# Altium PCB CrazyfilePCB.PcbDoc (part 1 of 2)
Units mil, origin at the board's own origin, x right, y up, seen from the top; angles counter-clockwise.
Board outline 3667.19 x 3670.52 mil, 4 copper layers (Top Layer, GND, VCC, Bottom Layer); 99 components, 96 nets, 358 pads, 80 vias.
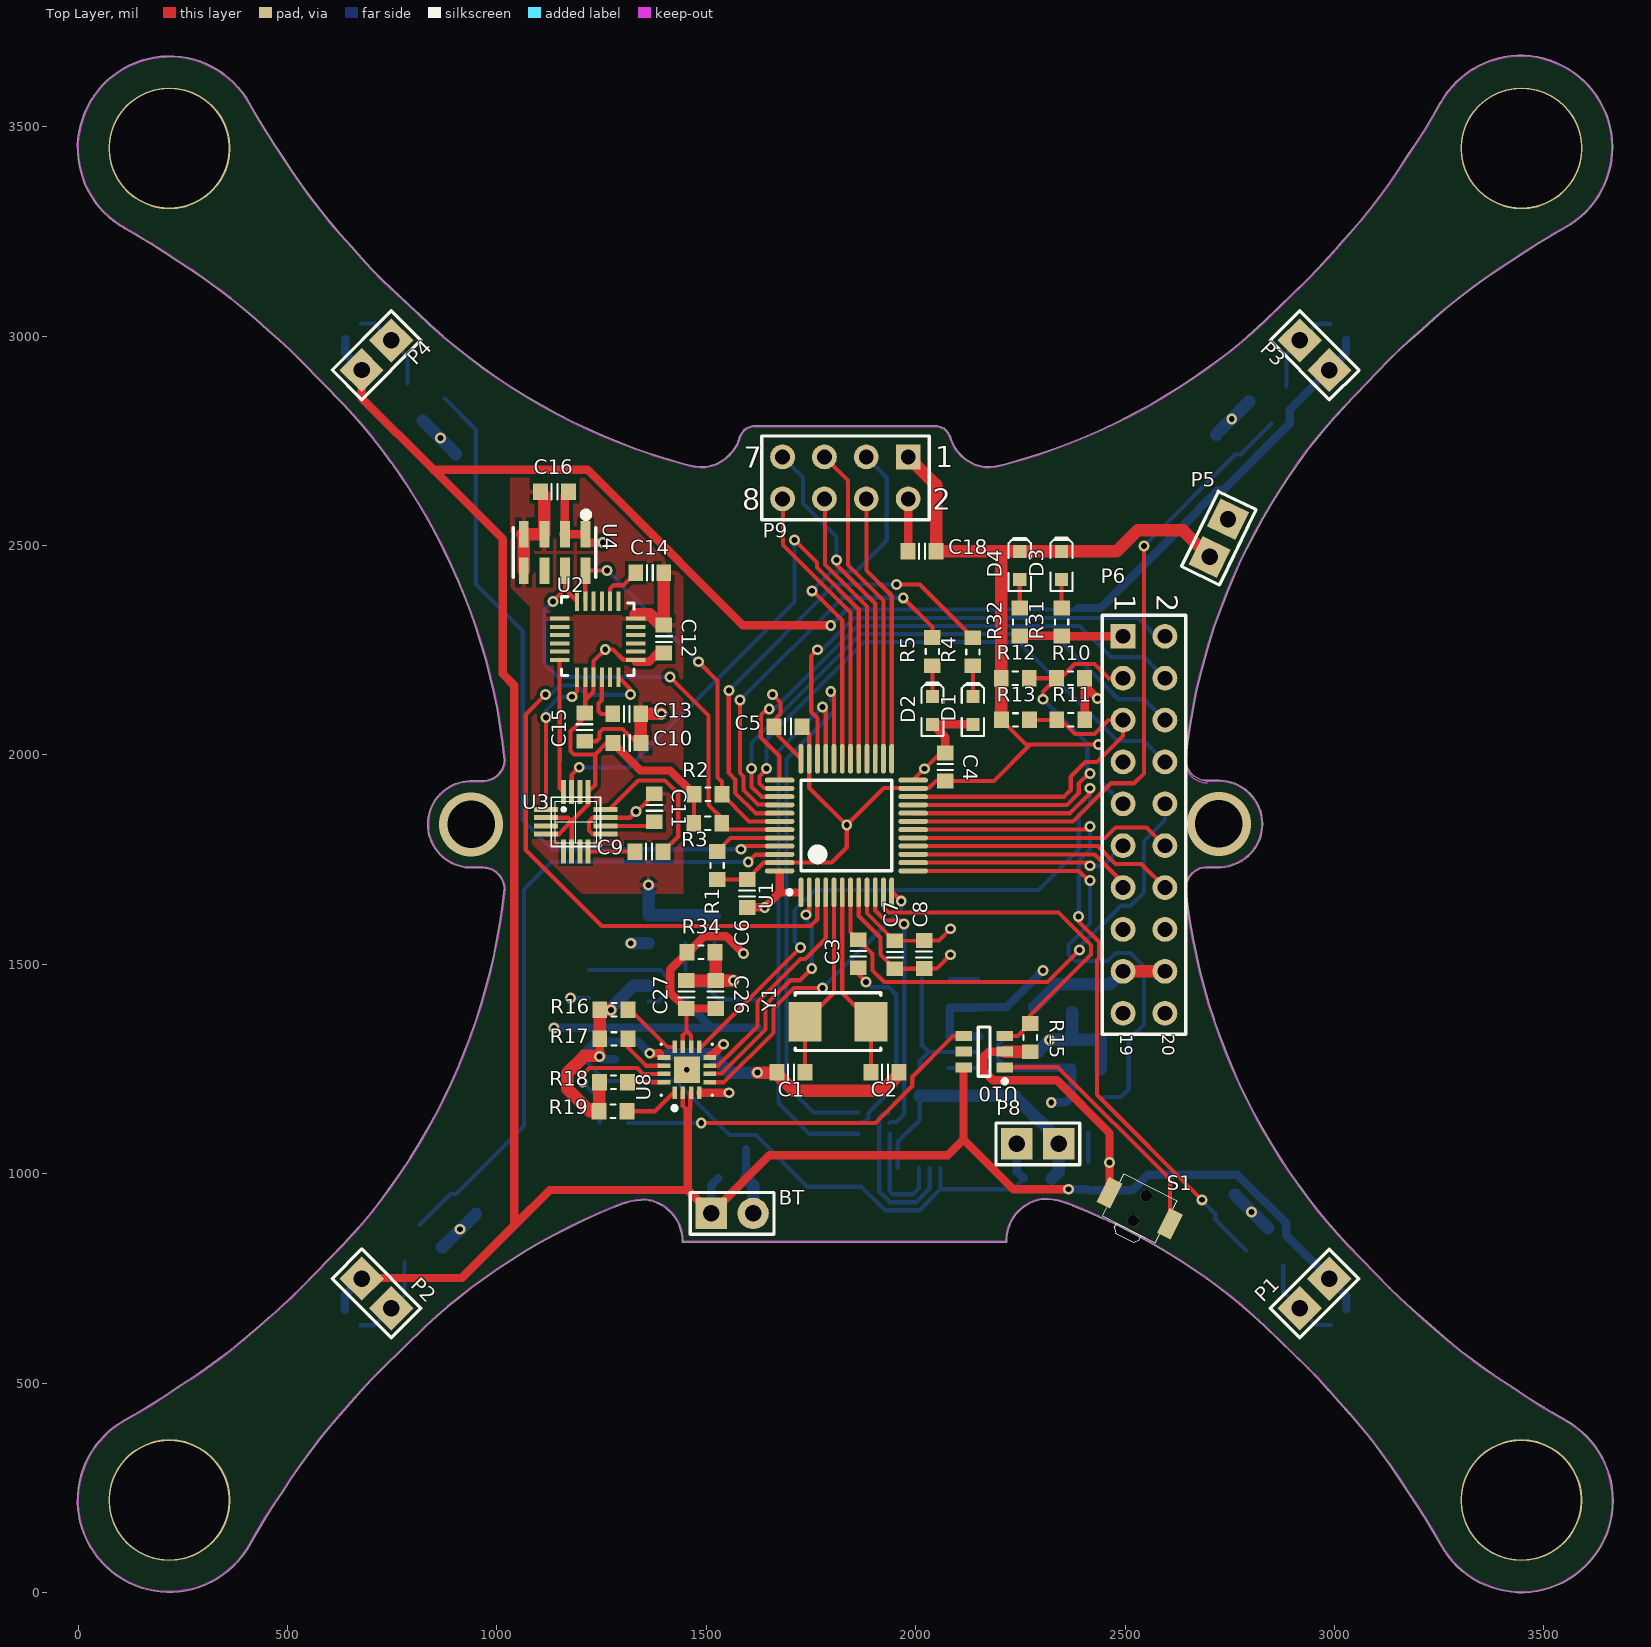
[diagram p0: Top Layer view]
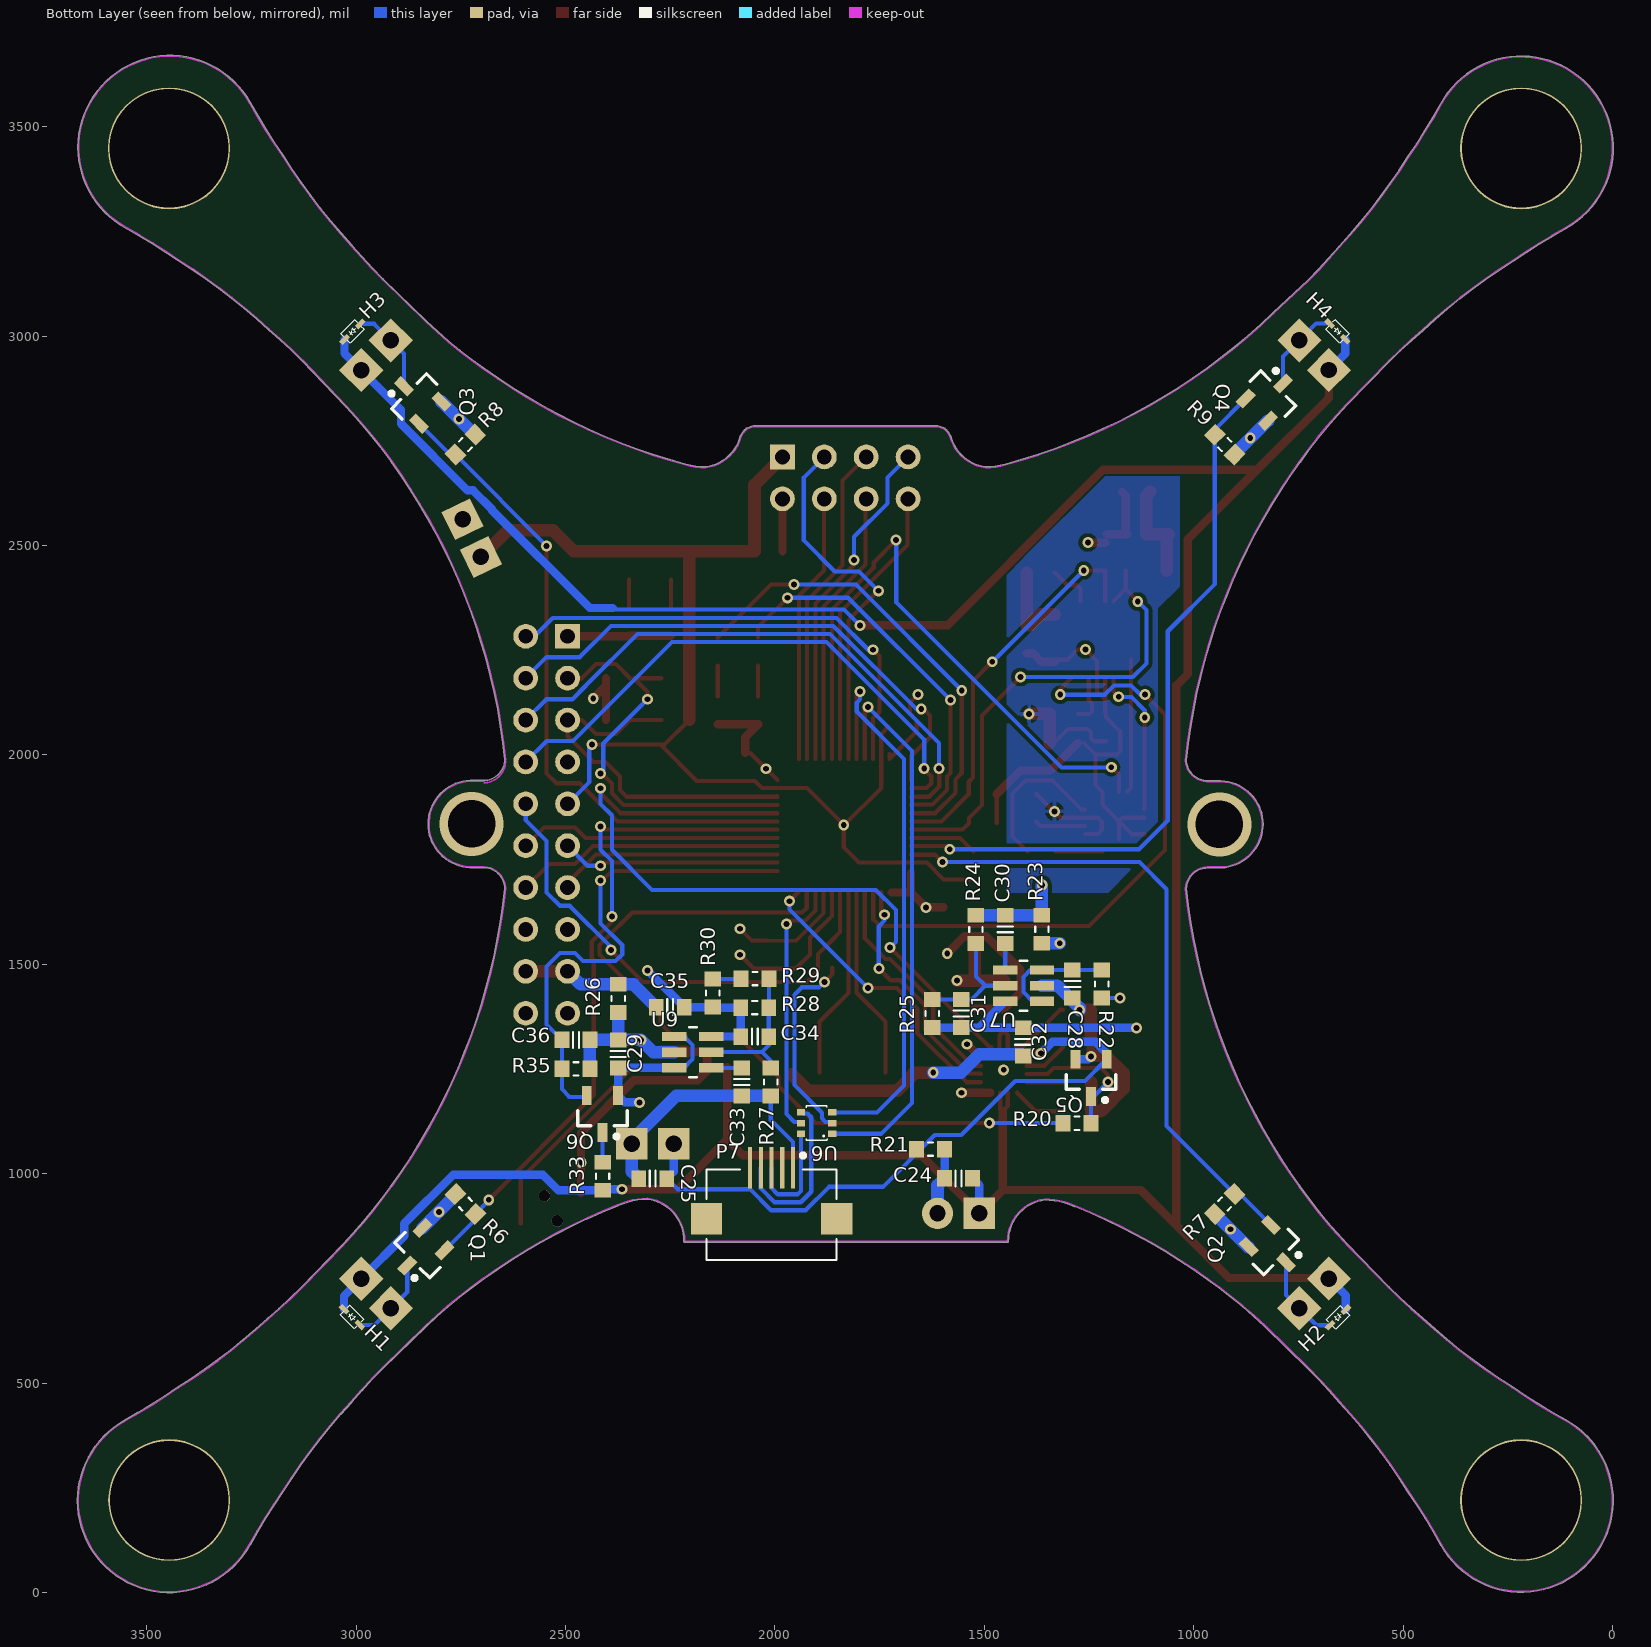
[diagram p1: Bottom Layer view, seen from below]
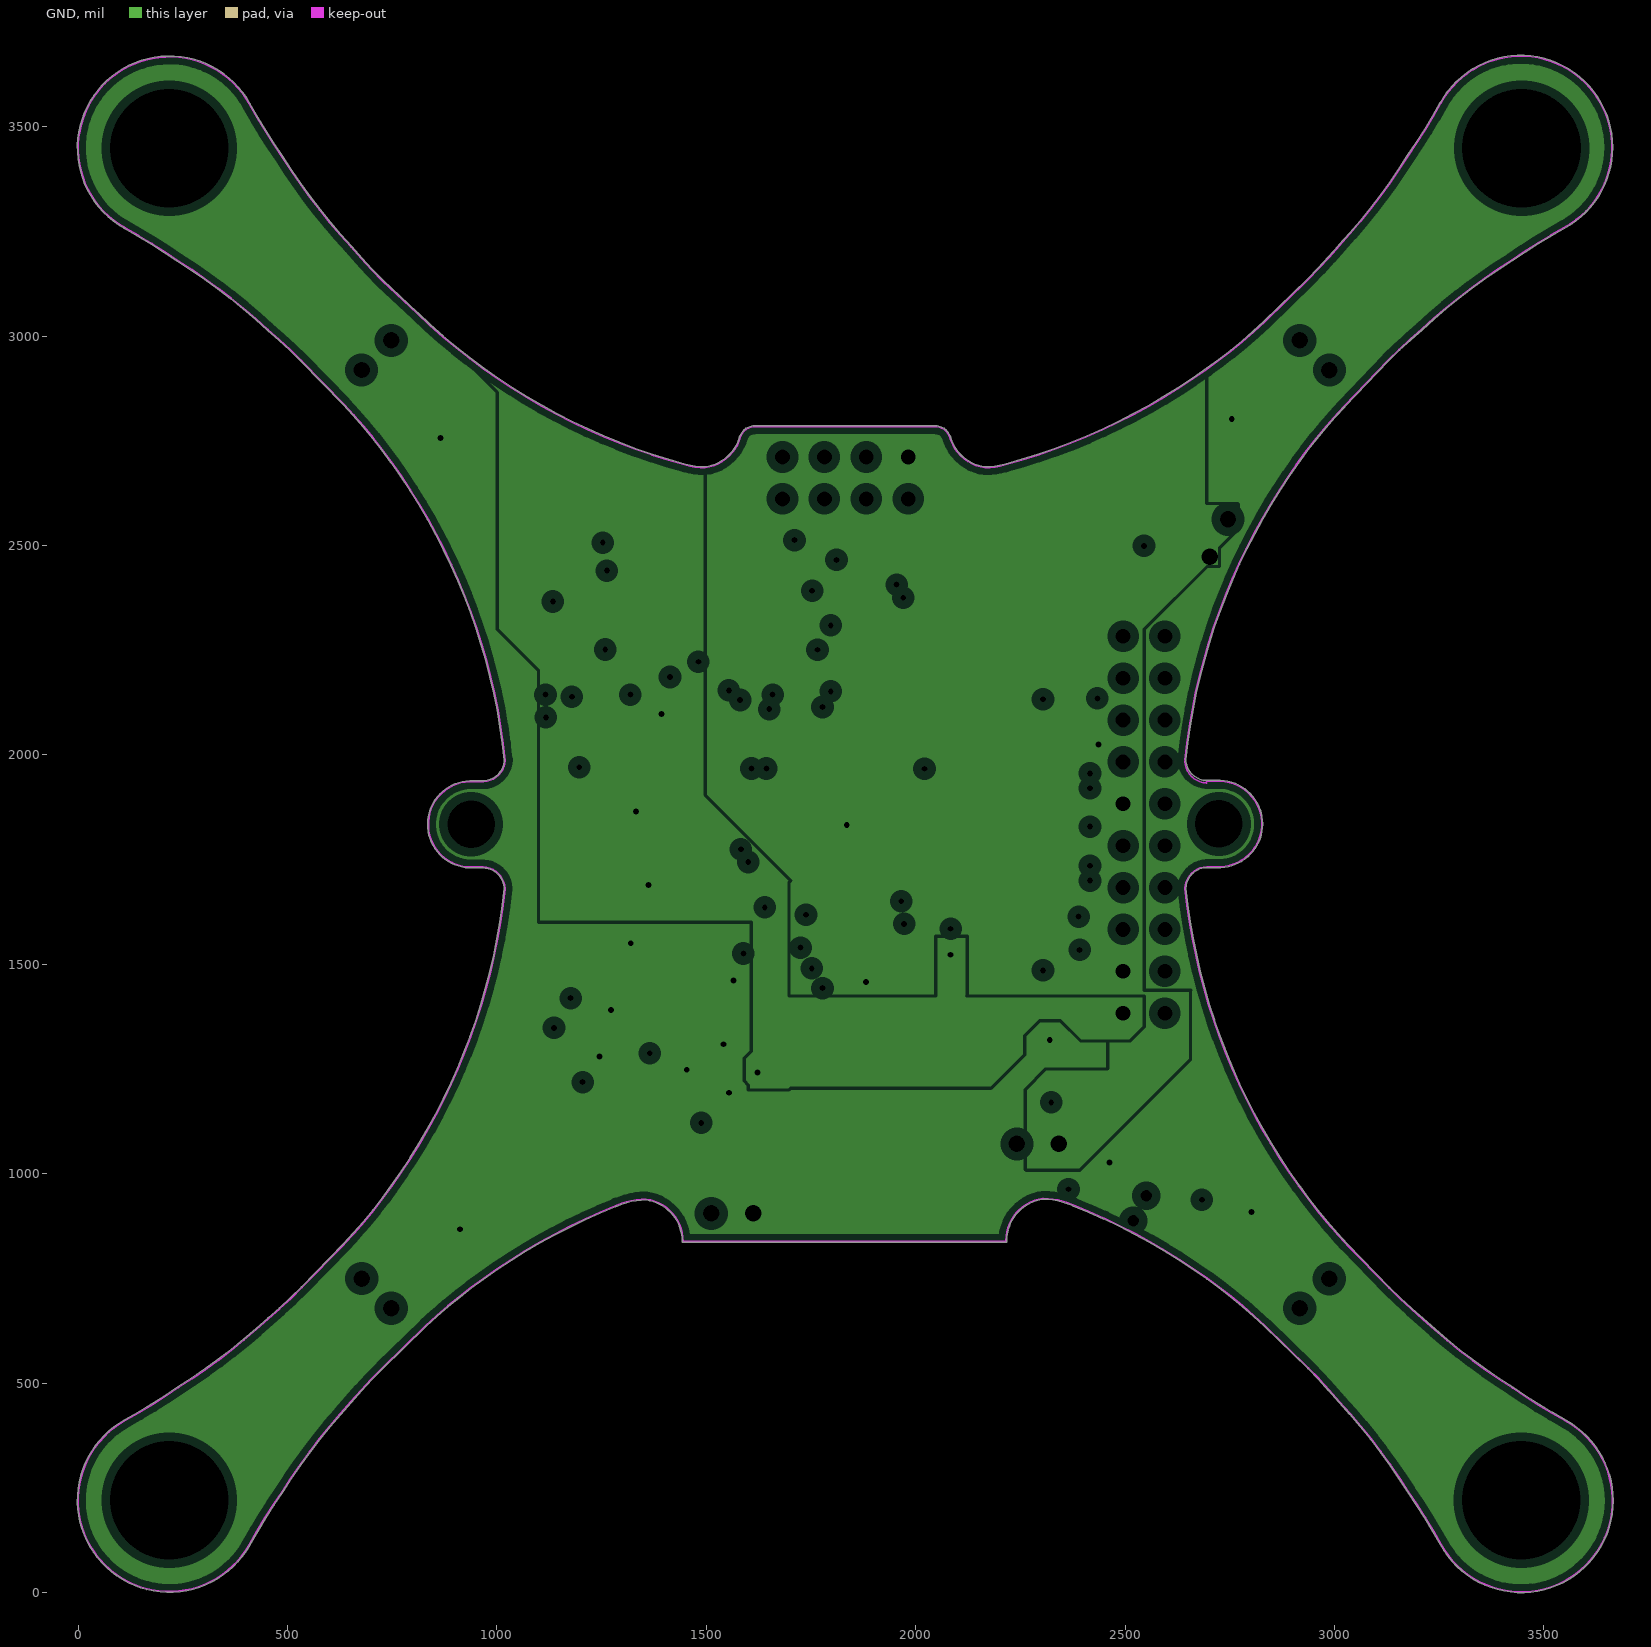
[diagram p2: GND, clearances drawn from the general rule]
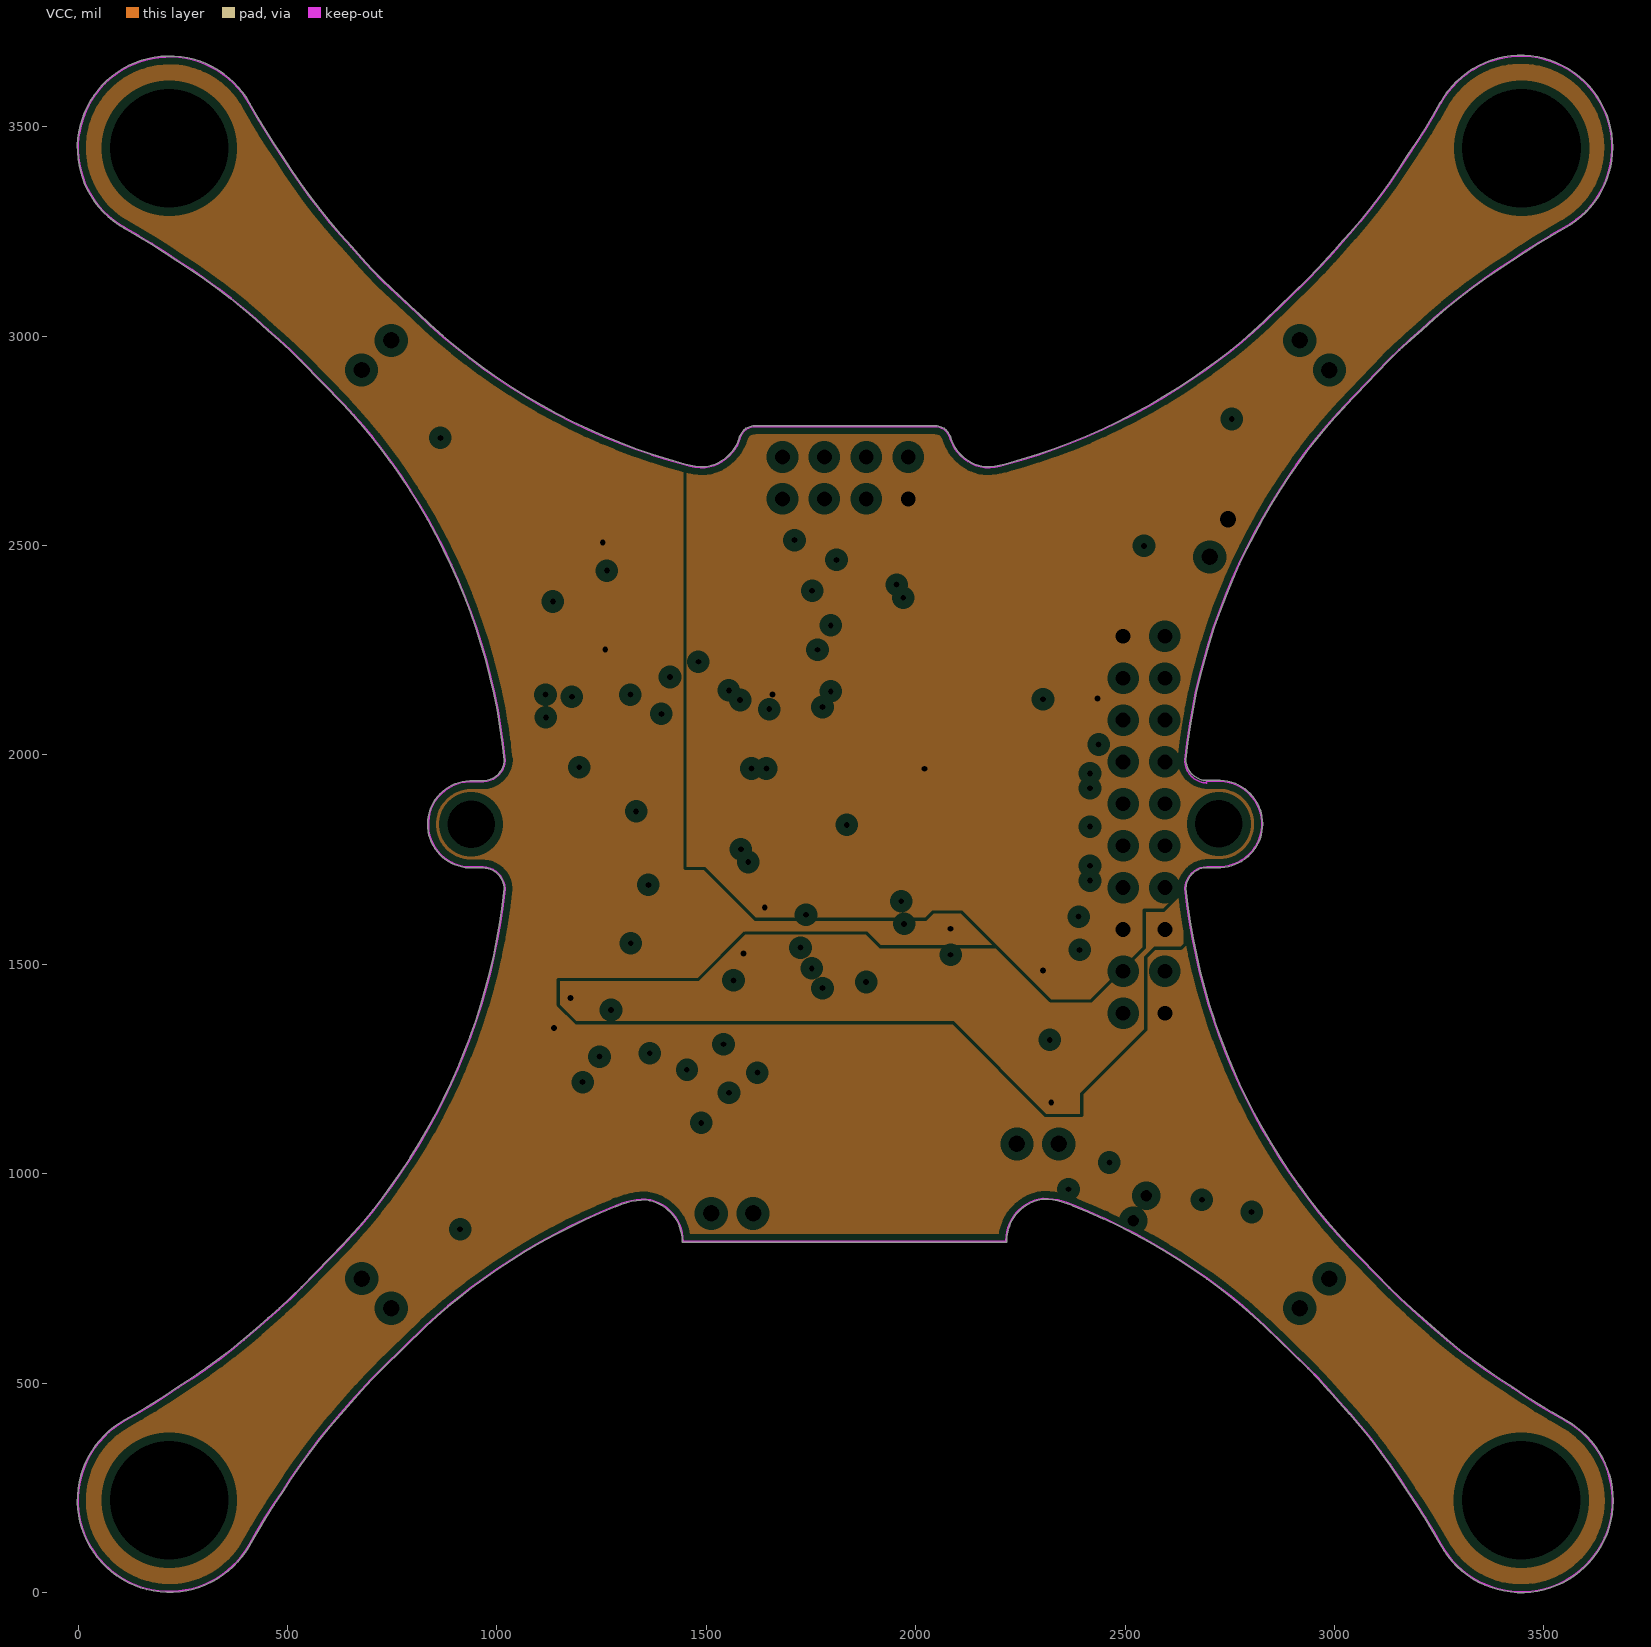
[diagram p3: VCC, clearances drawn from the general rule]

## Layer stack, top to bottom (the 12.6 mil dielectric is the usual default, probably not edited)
Top Layer: signal copper 1.4
Dielectric: core 12.6, FR-4, Dk 4.8
GND: plane copper 1.4, net (Multiple Nets)
Dielectric: prepreg 12.6, FR-4, Dk 4.8
VCC: plane copper 1.4, net (Multiple Nets)
Dielectric: core 12.6, FR-4, Dk 4.8
Bottom Layer: signal copper 1.4

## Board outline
112.49,412.56 ccw(c218.07,219.96) 409.62,112.5 ccw(c408.54,114.15) 410.27,113.19 cw(c1713.74,-607.99) 488.67,239.56 ccw(c487.04,240.69) 488.7,239.6 ccw(c487.05,240.7) 488.73,239.64 cw(c1713.74,-529.25) 652.96,453.91 ccw(c651.5,455.25) 653.04,454 cw(c1713.74,-450.51) 727.04,534.2 830.81,635.06 cw(c1674.37,-253.66) 968.41,747.86 ccw(c967.28,749.48) 968.43,747.87 ccw(c967.28,749.48) 968.44,747.88 cw(c1832.24,-448.94) 1284.14,921.5 ccw(c1283.4,923.34) 1285.22,922.56 ccw(c1286.18,924.29) 1286.99,922.48 cw(c1356.01,767.66) 1356.47,937.17 cw(c1342.79,838.21) 1442.7,838.21 cw(c1342.79,838.21) 1442.7,838.12 cw(c1342.79,838.21) 1442.7,838.1 cw(c1444.68,838.1) 1442.7,838.12 1442.7,838.1 ccw(c1444.68,838.1) 1444.73,836.12 2215.48,836.12 ccw(c2215.48,838.1) 2217.46,838.1 ccw(c2215.48,838.1) 2217.3,838.89 ccw(c2215.48,839.68) 2217.46,839.68 cw(c2317.36,839.78) 2303.82,938.76 ccw(c2303.55,940.73) 2303.94,938.78 ccw(c2304.34,940.73) 2304.34,938.74 cw(c2304.93,769.24) 2373.96,924.05 ccw(c2374.76,925.87) 2374.14,923.98 ccw(c2375.52,925.4) 2374.79,923.56 cw(c1832.24,-448.94) 2695.26,748.27 2695.27,748.27 ccw(c2696.42,749.88) 2695.28,748.26 cw(c1989.33,-253.27) 2832.89,635.45 2936.66,534.59 2936.67,534.58 2936.66,534.59 cw(c1949.96,-450.12) 3010.66,454.39 ccw(c3012.2,455.65) 3010.74,454.3 cw(c1949.96,-528.86) 3174.97,240.04 ccw(c3176.65,241.09) 3175,240 ccw(c3176.66,241.08) 3175.03,239.95 cw(c1949.96,-607.6) 3253.42,113.6 3253.43,113.59 ccw(c3446.02,219.17) 3665.66,219.17 ccw(c3446.02,219.17) 3553.49,410.72 ccw(c3551.83,409.64) 3552.79,411.37 cw(c4273.98,1714.84) 3426.42,489.77 ccw(c3425.3,488.14) 3426.38,489.8 ccw(c3425.28,488.15) 3426.34,489.83 cw(c4195.24,1714.84) 3212.08,654.06 ccw(c3210.73,652.6) 3211.98,654.14 cw(c4116.5,1714.84) 3131.79,728.14 3131.8,728.13 3131.79,728.14 3030.93,831.91 3030.92,831.92 3030.93,831.91 cw(c3919.65,1675.47) 2918.12,969.52 ccw(c2916.5,968.38) 2916.33,970.36 ccw(c2914.35,970.51) 2916.34,970.51 ccw(c2914.35,970.51) 2915.96,971.67 cw(c4113.74,1834.92) 2645.28,1681.58 ccw(c2643.31,1681.77) 2645.29,1681.68 cw(c2696.7,1679.41) 2695.21,1730.85 2728.56,1730.97 ccw(c2728.56,1732.95) 2728.84,1730.99 ccw(c2724.37,1834.92) 2828.4,1834.92 ccw(c2724.37,1834.92) 2727.84,1938.89 ccw(c2727.77,1936.91) 2727.49,1938.87 2694.76,1938.87 ccw(c2694.45,1936.91) 2694.52,1938.9 cw(c2696.42,1990.43) 2644.9,1988.16 ccw(c2642.91,1988.07) 2644.86,1988.43 cw(c4113.74,1834.92) 2916.58,2699.77 ccw(c2914.97,2700.93) 2916.95,2700.93 ccw(c2914.97,2700.93) 2916.95,2701.08 cw(c3929.95,1971.8) 3024.64,2831.12 ccw(c3023.2,2832.49) 3024.79,2831.3 ccw(c3023.75,2832.99) 3025.19,2831.63 3129.43,2941.31 cw(c4114.13,1954.61) 3209.62,3015.31 cw(c4114.13,1954.61) 3209.66,3015.34 3209.62,3015.31 ccw(c3208.37,3016.85) 3209.72,3015.39 cw(c4192.87,1954.61) 3423.98,3179.62 ccw(c3422.92,3181.3) 3424.02,3179.65 ccw(c3422.93,3181.31) 3424.06,3179.68 cw(c4271.61,1954.61) 3550.42,3258.07 ccw(c3444.84,3450.67) 3664.48,3450.67 ccw(c3444.84,3450.67) 3253.29,3558.13 ccw(c3254.38,3556.48) 3252.64,3557.44 cw(c1949.17,4278.62) 3174.24,3431.07 ccw(c3175.87,3429.94) 3174.21,3431.03 ccw(c3175.87,3429.93) 3174.19,3430.99 cw(c1949.17,4199.88) 3009.96,3216.72 ccw(c3011.41,3215.38) 3009.88,3216.63 ccw(c1949.17,4121.14) 3009.9,3216.66 3009.88,3216.63 cw(c1949.17,4121.14) 2935.87,3136.43 2935.88,3136.44 2935.87,3136.43 2832.11,3035.57 2832.1,3035.57 2832.11,3035.57 cw(c1988.54,3924.29) 2695.04,2923.15 ccw(c2695.56,2921.24) 2694.4,2922.85 cw(c1832.24,4117.99) 2213.23,2694.43 ccw(c2213.75,2692.51) 2213.19,2694.42 cw(c2165.91,2857.2) 2165.45,2687.69 cw(c2179.13,2786.65) 2082.44,2761.5 ccw(c2080.52,2761) 2081.59,2762.68 ccw(c2034.61,2740.04) 2069.04,2779.21 ccw(c2067.73,2777.72) 2067.97,2779.69 ccw(c2045.24,2740.04) 2044.03,2785.72 ccw(c2045.24,2740.04) 2044,2785.72 2044.06,2785.72 1618.89,2785.72 cw(c1617.68,2740.04) 1618.91,2785.72 1618.89,2785.72 ccw(c1617.68,2740.04) 1594.95,2779.69 ccw(c1595.18,2777.72) 1593.87,2779.21 ccw(c1628.31,2740.04) 1581.32,2762.68 ccw(c1582.39,2761) 1580.47,2761.5 cw(c1483.78,2786.65) 1497.46,2687.69 cw(c1497,2857.2) 1449.72,2694.42 1449.68,2694.43 cw(c1831.69,4115.93) 810.9,3055.47 ccw(c809.52,3054.04) 810.87,3055.5 810.88,3055.48 810.87,3055.5 727.43,3133.68 cw(c1714.13,4118.39) 653.43,3213.87 cw(c1714.13,4118.39) 653.4,3213.91 653.43,3213.87 ccw(c651.89,3212.62) 653.35,3213.97 cw(c1714.13,4197.13) 489.12,3428.23 ccw(c487.44,3427.17) 489.09,3428.27 ccw(c487.43,3427.19) 489.06,3428.31 cw(c1714.13,4275.87) 410.67,3554.67 ccw(c218.07,3449.09) 110.61,3257.54 ccw(c112.27,3258.63) 111.3,3256.89 cw(c-609.88,1953.43) 237.67,3178.5 ccw(c238.8,3180.13) 237.71,3178.47 ccw(c238.81,3180.12) 237.76,3178.44 cw(c-531.14,1953.43) 452.02,3014.21 ccw(c453.36,3015.66) 452.11,3014.13 cw(c-452.4,1953.43) 532.31,2940.12 532.3,2940.14 532.31,2940.12 633.17,2836.36 633.17,2836.35 633.17,2836.36 cw(c-255.55,1992.8) 745.97,2698.74 ccw(c747.59,2699.89) 747.06,2697.98 cw(c-450.83,1834.13) 1018.05,1987.65 ccw(c1020,1987.29) 1018.02,1987.37 cw(c966.5,1989.65) 968.39,1938.11 ccw(c968.46,1936.13) 968.15,1938.09 935.42,1938.09 ccw(c935.14,1936.12) 935.08,1938.1 ccw(c938.54,1834.13) 934.07,1730.2 ccw(c934.36,1732.17) 934.35,1730.18 967.7,1730.06 967.72,1730.06 967.7,1730.06 ccw(c966.22,1678.63) 967.68,1730.06 967.7,1730.06 cw(c966.22,1678.63) 1017.62,1680.9 ccw(c1019.61,1680.98) 1017.63,1680.79 cw(c-450.83,1834.13) 746.95,970.88 ccw(c748.56,969.72) 746.58,969.9 cw(c-254.37,1676.65) 634.35,833.09 634.35,833.1 634.35,833.09 533.49,729.32 cw(c-451.22,1716.02) 453.29,655.32 cw(c-451.22,1716.02) 453.26,655.29 453.29,655.32 ccw(c454.54,653.78) 453.2,655.24 cw(c-529.96,1716.02) 238.94,491.01 ccw(c239.99,489.33) 238.89,490.98 ccw(c239.98,489.32) 238.85,490.95 cw(c-608.7,1716.02)

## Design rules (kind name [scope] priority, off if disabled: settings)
Clearance U8 [Ispad and incomponent ( 'U8' )] p1: gap=6.4
Clearance U6 [Ispad and incomponent ( 'U6' )] p2: gap=9.8
Clearance U3 [IspaD and incomponent ( 'U3' )] p3: gap=6.4
Clearance U2 [Ispad and incomponent ( 'U2' )] p4: gap=9.7
Clearance U1 [Ispad and incomponent ( 'U1' )] p5: gap=7.8
Clearance [All] p6: gap=9
FabricationTestPointUsage TestPointUsage [All] p1: valid=0 allowmultiple=FALSE
FabricationTestpoint Testpoint [All] p1: side=3 testpointundercomponent=TRUE minsize=40 maxsize=100 preferedsize=60 minholesize=0 maxholesize=40 preferedholesize=32 testpointgrid=1 allowsidetop=TRUE allowsidebottom=TRUE usegrid=TRUE gridtolerance=0.01
HoleSize [All] p1: absolutevalues=TRUE maxlimit=200 minlimit=1 maxpercent=80.000 minpercent=20.000
PlaneClearance [All] p1: clearance=20
PlaneConnect [All] p1: planeconnectstyle=Relief reliefexpansion=20 reliefentries=4 reliefconductorwidth=10 reliefairgap=10
PolygonConnect [All] p1: connectstyle=Relief reliefconductorwidth=10 reliefentries=4 polygonreliefangle="90 Angle"
RoutingVias [All] p1: holewidth=28 width=50 viastyle="Through Hole" minholewidth=28 minwidth=50 maxholewidth=228 maxwidth=250
SilkscreenOverComponentPads [All] p1: minsilkscreentomaskgap=10
SolderMaskExpansion [All] p1: expansion=4
Width VCC_Width [InNet('VCC')] p1: maxlimit=30 minlimit=10 preferedwidth=20
Width POWER_5V_Width [InNet('VCOM')] p2: maxlimit=30 minlimit=10 preferedwidth=20
Width POWER_3V3_Width [InNet('VCCA')] p3: maxlimit=30 minlimit=9 preferedwidth=20
Width GND_Width [InNet('GND')] p4: maxlimit=40 minlimit=10 preferedwidth=30
Width Width_+BATT [InNet('+BATT')] p5: maxlimit=30 minlimit=10 preferedwidth=20
22 further rules are at their usual default settings.

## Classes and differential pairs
component class "crazefile contal wireless": C18 P9
component class "crazefile contal power": BT C24 C25 C26 C27 C28 C29 C30 C31 C32 C33 C34 C35 C36 D3 D4 P7 P8 Q5 Q6 R15 R16 R17 R18 R19 R20 R21 R22 R23 R24 R25 R26 R27 R28 R29 R30 R31 R32 R33 R34 R35 S1 U6 U7 U8 U9 U10
component class "crazefile contal imu": C9 C10 C11 C12 C13 C14 C15 C16 U2 U3 U4
component class "crazefile contal board": C1 C2 C3 C4 C5 C6 C7 C8 D1 D2 H1 H2 H3 H4 P1 P2 P3 P4 P5 P6 Q1 Q2 Q3 Q4 R1 R2 R3 R4 R5 R6 R7 R8 R9 R10 R11 R12 R13 U1 Y1

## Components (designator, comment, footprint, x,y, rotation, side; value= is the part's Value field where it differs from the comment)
BT "Battery" BATTERY 1511.9,905 r0 top locked
C1 "Cap" CAP_0603 1702.12,1241.73 r0 top
C2 "Cap" CAP_0603 1926.82,1241.73 r180 top
C3 "Cap" CAP_0603 1863.08,1525.04 r270 top
C4 "Cap" CAP_0603 2070.78,1971.25 r90 top
C5 "Cap" CAP_0603 1695.12,2067.48 r0 top
C6 "Cap" CAP_0603 1597.45,1669.24 r270 top
C7 "Cap" CAP_0603 1950.56,1522.64 r90 top
C8 "Cap" CAP_0603 2020.11,1523.07 r270 top
C9 "Cap" CAP_0603 1363.47,1769.03 r180 top
C10 "Cap" CAP_0603 1310.44,2028.33 r180 top
C11 "Cap" CAP_0603 1376.18,1873.6 r270 top
C12 "Cap" CAP_0603 1399.01,2276.3 r90 top
C13 "Cap" CAP_0603 1310.17,2097.71 r180 top
C14 "Cap" CAP_0603 1365.19,2434.82 r180 top
C15 "Cap" CAP_0603 1209.37,2066.11 r90 top
C16 "Cap" CAP_0603 1137.89,2628.11 r0 top
C18 "Cap" CAP_0603 2015.5,2486.08 r180 top
C24 "Cap" CAP_0603 1561.9,988.73 r180 bottom
C25 "Cap" CAP_0603 2291.93,988.26 r0 bottom
C26 "Cap" CAP_0603 1522.47,1427.65 r270 top
C27 "Cap" CAP_0603 1452.52,1427.76 r270 top
C28 "Cap" CAP_0603 1289.76,1452.69 r90 bottom
C29 "Cap" CAP_0603 2374.37,1285.83 r270 bottom
C30 "Cap" CAP_0603 1450.18,1583.38 r270 bottom
C31 "Cap" CAP_0603 1555.12,1382.26 r270 bottom
C32 "Cap" CAP_0603 1407.41,1314.74 r90 bottom
C33 "Cap" CAP_0603 2079.3,1219.13 r90 bottom
C34 "Cap" CAP_0603 2048.2,1327.43 r0 bottom
C35 "Cap" CAP_0603 2250.18,1397.86 r0 bottom
C36 "Cap" CAP_0603 2475.37,1319.23 r0 bottom
D1 "LED0" LED_0603_GREEN 2136.67,2105.81 r90 top
D2 "LED0" LED_0603_RED 2040.19,2106.21 r90 top
D3 "LED0" LED_0603_GREEN 2348.23,2452.49 r90 top
D4 "LED0" LED_0603_RED 2248.58,2452.36 r90 top
H1 "BAT54" SOD-523 2982.34,629.64 r45 bottom locked
H2 "BAT54" SOD-523 683.46,628.74 r135 bottom locked
H3 "BAT54" SOD-523 2981.14,3038.46 r315 bottom locked
H4 "BAT54" SOD-523 684.76,3039.06 r225 bottom locked
P1 "Header 2" HDR1X2_180_2.54 2917.09,678.39 r45 top locked
P2 "Header 2" HDR1X2_180_2.54 677.19,749.41 r315 top locked
P3 "Header 2" HDR1X2_180_2.54 2988.11,2918.89 r135 top locked
P4 "Header 2" HDR1X2_180_2.54 747.81,2989.71 r225 top locked
P5 "Header 2" HDR1X2_180_2.54 2745.9,2562.5 r244 top locked
P6 "Header 10X2" HDR2X10 2495.29,2283.1 r270 top
P7 "MICRO-B-USB" USB_MICRO_B 2008.2,1013.8 r270 bottom locked
P8 "Header 2" HDR1X2_180_2.54 2341.83,1070.97 r180 top
P9 "Header 4X2" HDR2X4 1982.2,2711.3 r180 top locked
Q1 "2N7002" SI2302#1 2846.33,811.67 r315 bottom locked
Q2 "2N7002" SI2302#1 810.47,819.97 r225 bottom locked
Q3 "2N7002" SI2302#1 2854.93,2848.33 r45 bottom locked
Q4 "2N7002" SI2302#1 818.27,2856.23 r135 bottom locked
Q5 "2N7002" SI2302#2 1244.64,1228.7 r270 bottom
Q6 "2N7002" SI2302#2 2411.35,1141.92 r270 bottom
R1 "Res2" RES_0603 1525.92,1736.01 r90 top
R2 "Res2" RES_0603 1503.9,1906.15 r180 top
R3 "Res2" RES_0603 1503.52,1836.63 r180 top
R4 "Res2" RES_0603 2136.81,2246.06 r270 top
R5 "Res2" RES_0603 2040.19,2246.41 r270 top
R6 "Res2" RES_0603 2739.01,927.36 r225 bottom locked
R7 "Res2" RES_0603 926.14,927.63 r135 bottom locked
R8 "Res2" RES_0603 2739.43,2740.93 r315 bottom locked
R9 "Res2" RES_0603 925.99,2740.78 r45 bottom locked
R10 "Res2" RES_0603 2370.08,2183.06 r180 top
R11 "Res2" RES_0603 2370.32,2083.48 r180 top
R12 "Res2" RES_0603 2238.02,2183.13 r0 top
R13 "Res2" RES_0603 2238.26,2083.36 r180 top
R15 "Res2" RES_0603 2273.43,1324.69 r90 top
R16 "Res2" RES_0603 1279.34,1391.2 r0 top
R17 "Res2" RES_0603 1279.34,1321.6 r0 top
R18 "Res2" RES_0603 1278.23,1218.52 r0 top
R19 "Res2" RES_0603 1277.64,1148.88 r0 top
R20 "Res2" RES_0603 1279,1120.64 r180 bottom
R21 "Res2" RES_0603 1628.4,1058.62 r0 bottom
R22 "Res2" RES_0603 1219.99,1452.69 r270 bottom
R23 "Res2" RES_0603 1362.51,1583.57 r270 bottom
R24 "Res2" RES_0603 1520,1583.41 r270 bottom
R25 "Res2" RES_0603 1624.4,1382.26 r270 bottom
R26 "Res2" RES_0603 2373.97,1418.63 r90 bottom
R27 "Res2" RES_0603 2009.9,1218.73 r90 bottom
R28 "Res2" RES_0603 2048.18,1396.54 r0 bottom
R29 "Res2" RES_0603 2047.98,1465.84 r0 bottom
R30 "Res2" RES_0603 2148.88,1431.46 r270 bottom
R31 "Res2" RES_0603 2348.43,2316.93 r270 top
R32 "Res2" RES_0603 2248.58,2317.54 r270 top
R33 "Res2" RES_0603 2411.8,993.7 r270 bottom locked
R34 "Res2" RES_0603 1487.82,1528.36 r180 top
R35 "Res2" RES_0603 2475.37,1249.93 r0 bottom
S1 "SW-PB" SKREHE010 2622.7,872.9 r153 top locked
U1 "STM32F103CBT6" LQFP48_N 1834.62,1831.25 r90 top locked
U2 "MPU6050" MPU9150 1240.82,2276.17 r0 top
U3 "HMC5883L" HMC5883L 1129.48,1781 r0 top
U4 "MS5611-01BA03" FQN8 1258.79,2478.31 r270 top
U6 "NUF2221" SOT363 1900.61,1120.92 r0 bottom
U7 "TPS79301" DBV6 1406.88,1450.28 r0 bottom
U8 "BQ24075" QFN17 1453.93,1247.93 r90 top
U9 "TPS79301" DBV6 2195.8,1288.63 r180 bottom
U10 "MAX16054" SOT23-6 2163.61,1291.29 r180 top
Y1 "XTAL_5032" XTAL_5032 1814.67,1362.83 r0 top

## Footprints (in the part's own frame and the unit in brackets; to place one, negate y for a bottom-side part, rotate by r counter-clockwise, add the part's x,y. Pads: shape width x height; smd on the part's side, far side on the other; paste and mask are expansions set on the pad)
BATTERY [mm]
  rect 1.905x1.905 hole 1: 1(0,0)
  round 1.905 hole 1: 2(2.54,0)
  silkscreen extent -1.27,-1.27 3.81,1.27
CAP_0603 [mm]
  rect 0.9x1 smd: 1(-0.85,0) 2(0.85,0)
  Top Layer pour cut-out: -0.4,0.6 0.4,0.6 0.4,-0.6 -0.4,-0.6
  silkscreen extent -0.18,-0.48 0.18,0.48
DBV6 [mil]
  rect 58x22 smd: 1(-44.51,38.86) 2(-44.51,1.46) 3(-44.51,-35.95) 4(43.49,-35.95) 5(43.49,1.46) 6(43.49,38.86)
  silkscreen extent -9,-59 8,61
FQN8 [mm]
  rect 1.6x0.6 smd: 1(-1.227,-1.195) 2(-1.227,-2.445) 3(-1.227,-3.695) 4(-1.227,-4.945) 5(0.973,-4.945) 6(0.973,-3.695) 7(0.973,-2.445) 8(0.973,-1.195)
  silkscreen extent -2.54,-5.57 1.37,-0.57
HDR1X2_180_2.54 [mm]
  rect 1.905x1.905 hole 1: 1(0,0) 2(2.54,0)
  silkscreen extent -1.27,-1.27 3.81,1.27
HDR2X4 [mm] "Connector; Header; 4x2 Position"
  rect 1.5x1.5 hole 0.9: 1(0,0)
  round 1.5 hole 0.9: 2(0,2.54) 3(2.54,0) 4(2.54,2.54) 5(5.08,0) 6(5.08,2.54) 7(7.62,0) 8(7.62,2.54)
  silkscreen extent -1.27,-1.27 8.89,3.81
HDR2X10 [mm] "Connector; Header; 10x2 Position"
  rect 1.5x1.5 hole 0.9: 1(0,0)
  round 1.5 hole 0.9: 2(0,2.54) 3(2.54,0) 4(2.54,2.54) 5(5.08,0) 6(5.08,2.54) 7(7.62,0) 8(7.62,2.54) 9(10.16,0) 10(10.16,2.54) 11(12.7,0) 12(12.7,2.54) 13(15.24,0) 14(15.24,2.54) 15(17.78,0) 16(17.78,2.54) 17(20.32,0) 18(20.32,2.54) 19(22.86,0) 20(22.86,2.54)
  silkscreen extent -1.27,-1.27 24.13,3.81
HMC5883L [mm]
  rect 1.45x0.3 smd: 1(-0.31,2.25) 2(-0.31,1.75) 3(-0.31,1.25) 4(-0.31,0.75) 9(3.31,0.75) 10(3.31,1.25) 11(3.31,1.75) 12(3.31,2.25)
  rect 0.3x1.45 smd: 5(0.75,-0.31) 6(1.25,-0.31) 7(1.75,-0.31) 8(2.25,-0.31) 13(2.25,3.32) 14(1.75,3.32) 15(1.25,3.32) 16(0.75,3.32)
  silkscreen extent 0,0 3,3
LED_0603_GREEN [mm]
  rect 0.8x0.8 smd: 1(-0.85,0) 2(0.85,0)
  Top Layer pour cut-out: -0.5,0.5 0.5,0.5 0.5,-0.5 -0.5,-0.5
  silkscreen extent -1.55,-0.67 1.67,0.68
LED_0603_RED [mm]
  rect 0.8x0.8 smd: 1(-0.85,0) 2(0.85,0)
  Top Layer pour cut-out: -0.5,0.5 0.5,0.5 0.5,-0.5 -0.5,-0.5
  silkscreen extent -1.55,-0.67 1.67,0.68
LQFP48_N [mm] "Thin QFP, 48-Leads, Body 7x7mm, Pitch 0.5mm, IPC Medium Density"
  oval 1.8x0.3 smd: 1(-4.05,2.75) 2(-4.05,2.25) 3(-4.05,1.75) 4(-4.05,1.25) 5(-4.05,0.75) 6(-4.05,0.25) 7(-4.05,-0.25) 8(-4.05,-0.75) 9(-4.05,-1.25) 10(-4.05,-1.75) 11(-4.05,-2.25) 12(-4.05,-2.75) 25(4.05,-2.75) 26(4.05,-2.25) 27(4.05,-1.75) 28(4.05,-1.25) 29(4.05,-0.75) 30(4.05,-0.25) 31(4.05,0.25) 32(4.05,0.75) 33(4.05,1.25) 34(4.05,1.75) 35(4.05,2.25) 36(4.05,2.75)
  oval 0.3x1.8 smd: 13(-2.75,-4.05) 14(-2.25,-4.05) 15(-1.75,-4.05) 16(-1.25,-4.05) 17(-0.75,-4.05) 18(-0.25,-4.05) 19(0.25,-4.05) 20(0.75,-4.05) 21(1.25,-4.05) 22(1.75,-4.05) 23(2.25,-4.05) 24(2.75,-4.05) 37(2.75,4.05) 38(2.25,4.05) 39(1.75,4.05) 40(1.25,4.05) 41(0.75,4.05) 42(0.25,4.05) 43(-0.25,4.05) 44(-0.75,4.05) 45(-1.25,4.05) 46(-1.75,4.05) 47(-2.25,4.05) 48(-2.75,4.05)
  silkscreen extent -4.17,-2.75 2.75,3.57, body extent -3.5,-3.5 3.5,3.5, height 1.6
MPU9150 [mm]
  rect 1.2x0.245 smd: 1(-2.304,1.25) 2(-2.304,0.75) 3(-2.304,0.25) 4(-2.304,-0.25) 5(-2.304,-0.75) 6(-2.304,-1.25) 13(2.304,-1.25) 14(2.304,-0.75) 15(2.304,-0.25) 16(2.304,0.25) 17(2.304,0.75) 18(2.304,1.25)
  rect 0.245x1.2 smd: 7(-1.25,-2.304) 8(-0.75,-2.304) 9(-0.25,-2.304) 10(0.25,-2.304) 11(0.75,-2.304) 12(1.25,-2.304) 19(1.25,2.304) 20(0.75,2.304) 21(0.25,2.304) 22(-0.25,2.304) 23(-0.75,2.304) 24(-1.25,2.304)
  silkscreen extent -2.2,-2.2 2.2,2.58
QFN17 [mm]
  rect 0.77x0.28 smd: 1(-1.39,0.75) 2(-1.39,0.25) 3(-1.39,-0.25) 4(-1.39,-0.75) 9(1.39,-0.75) 10(1.39,-0.25) 11(1.39,0.25) 12(1.39,0.75)
  rect 0.28x0.77 smd: 5(-0.75,-1.39) 6(-0.25,-1.39) 7(0.25,-1.39) 8(0.75,-1.39) 13(0.75,1.39) 14(0.25,1.39) 15(-0.25,1.39) 16(-0.75,1.39)
  rect 1.6x1.6 smd: 17(0,0)
  silkscreen extent -2.45,-1.55 1.55,1.55, body extent -1.55,-1.55 1.55,1.55, height 1
RES_0603 [mm]
  rect 0.9x1 smd: 1(-0.85,0) 2(0.85,0)
  Top Layer pour cut-out: -0.4,0.6 0.4,0.6 0.4,-0.6 -0.4,-0.6
  silkscreen extent -0.15,-0.41 0.15,0.41
SI2302#1 [mm]
  rect 1.15x0.6 smd: 1(1.122,-0.016) 2(-1.128,0.939) 3(-1.128,-0.966)
  silkscreen extent -0.2,-1.52 1.47,1.48, body extent -0.7,-1.52 0.7,1.48, height 1.1
SI2302#2 [mm]
  rect 1.15x0.6 smd: 1(-1.128,0.934) 2(-1.128,-0.966) 3(1.122,-0.016)
  silkscreen extent -0.2,-1.52 1.47,1.48, body extent -0.7,-1.52 0.7,1.48, height 1.1
SKREHE010 [mm]
  round 0.7 hole 0.7: 0(2.49,0.86) 0(2.49,-0.85)
  rect 0.9x1.7 smd: 1(4.55,0) 2(0.44,0)
  silkscreen extent 0.69,-1.44 4.3,2.01
SOD-523 [mm]
  rect 0.65x0.3 smd: 1(0.33,0) 2(1.676,0)
  silkscreen extent 0.4,-0.4 1.6,0.4
SOT23-6 [mm] "SOT23, 6-Leads, Body 3.0x3.0mm (max), Pitch 0.95mm, IPC Medium Density"
  rect 1x0.6 smd: 1(-1.25,0.95) 2(-1.25,0) 3(-1.25,-0.95) 4(1.25,-0.95) 5(1.25,0) 6(1.25,0.95)
  silkscreen extent -1.37,-1.5 0.35,1.92, body extent -0.85,-1.5 0.85,1.5, height 1.44
SOT363 [mm]
  rect 0.5x0.4 smd: 1(-0.952,0.656) 2(-0.952,0.006) 3(-0.952,-0.644) 4(0.948,-0.644) 5(0.948,0.006) 6(0.948,0.656)
  silkscreen extent -0.63,-1.04 0.62,1.06
USB_MICRO_B [mm]
  rect 2.5x0.25 smd: 1(0,-1.3) 2(0,-0.65) 3(0,0) 4(0,0.65) 5(0,1.3)
  rect 1.9x1.9 smd: ""(3.095,-3.95) ""(3.095,3.95)
  silkscreen extent -0.87,-3.94 5.6,3.94
XTAL_5032 [mm]
  rect 2x2.4 smd: 1(-2,0) 2(2,0)
  silkscreen extent -2.6,-1.75 2.6,1.75

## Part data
BT: "Multicell Battery"
C1 C2 C3 C4 C5 C6 C7 C8 C9 C10 C11 C12 C13 C14 C15 C16 C18 C24 C25 C26 C27 C28 C29 C30 C31 C32 C33 C34 C35 C36: "Capacitor"
D1 D2 D3 D4: "Typical INFRARED GaAs LED"
H1 H2 H3 H4: "Schottky Diode"
P1 P2 P3 P4 P5 P8: "Header, 2-Pin"
P6: "Header, 10-Pin, Dual row"
P7: library part MHDR1X5, "Header, 5-Pin"
P9: "Header, 4-Pin, Dual row"
Q1 Q2 Q3 Q4 Q5 Q6: library part SI2302_1
R1 R2 R3 R4 R5 R6 R7 R8 R9 R10 R11 R12 R13 R15 R16 R17 R18 R19 R20 R21 R22 R23 R24 R25 R26 R27 R28 R29 R30 R31 R32 R33 R34 R35: "Resistor"
S1: "Switch"
U1: "STM32 ARM-based 32-bit MCU with 128 Kbytes Flash, 48-pin LQFP, Industrial Temperature"
Y1: "Crystal Oscillator"

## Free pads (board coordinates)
  round 291.34 hole 283.46: 0(218.07,3448.31) 1(3446.81,3448.31) 2(3446.44,220.33) 3(218.07,220.35)

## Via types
v1: diameter 25.98, hole 14, Top Layer to Bottom Layer, tented both sides, 77 vias
v2: diameter 152.84, hole 113.47, Top Layer to Bottom Layer, 2 vias
v3: diameter 25.98, hole 12.99, Top Layer to Bottom Layer, tented top, 1 vias

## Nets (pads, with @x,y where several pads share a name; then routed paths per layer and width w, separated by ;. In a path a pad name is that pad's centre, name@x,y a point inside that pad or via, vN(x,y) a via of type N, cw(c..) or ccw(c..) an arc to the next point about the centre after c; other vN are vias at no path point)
+BATT: BT.1 C24.2 H1.2 H2.2 H3.2 H4.2 P1.2 P2.1 P3.1 P4.2 R33.2 U8.2 U8.3 U10.6 | length 8340.8
  Top Layer w10: U8.2@1444.09,1193.21 1444.09,1161.23 1455.85,1149.47 1461.98,1155.6 U8.3@1461.98,1193.21
  Top Layer w20: P4.2@677.1,2919 677.1,2852.43 848.43,2681.1 ; P2.1@677.19,749.41 678.51,750.74 916.2,750.74 1041.59,876.12 ; 1455.85,1149.47 1455.85,961.05 ; v1(1797.24,2309.06) 1587.6,2309.06 1435.37,2461.28 1435.37,2462.37 1216.64,2681.1 848.43,2681.1 ; U10.6@2114.4,1253.89 2114.4,1081.46 ; v1(2365.16,962.6) 2233.27,962.6 2114.4,1081.46 ; 848.43,2681.1 1014.24,2515.29 1014.24,2193.23 1041.59,2165.87 1041.59,876.12 ; 1041.59,876.12 1126.52,961.05 1455.85,961.05 ; 1455.85,961.05 BT.1@1511.9,905 1651.19,1044.29 2077.23,1044.29 2114.4,1081.46
  Bottom Layer w10: v1(1797.24,2309.06) 1835.63,2347.44 2387.8,2347.44
  Bottom Layer w20: H2.2@636.79,675.41 636.79,709.02 P2.1@677.19,749.41 ; H4.2@638.09,2992.39 638.09,2958.01 P4.2@677.1,2919 ; BT.1@1511.9,905 1511.9,972.2 C24.2@1528.44,988.73 ; v1(2365.16,962.6) 2409.44,962.6 R33.2@2411.8,960.24 2517.2,960.24 2554.01,997.05 ; 2387.8,2350.63 2442.13,2350.63 2676.76,2585.25 2676.76,2587.64 2720.76,2631.64 2734.1,2631.64 2893.03,2790.58 2893.03,2823.81 P3.1@2988.11,2918.89 3027.81,2958.58 H3.2@3027.81,2991.79 ; 2559.06,997.05 2768.58,997.05 2885.18,880.45 2885.18,851.71 P1.2@2987.8,749.1 3029.01,707.89 H1.2@3029.01,676.31
AGND: C1.1 C2.1 C7.1 C8.2 C10.1 C11.1 C12.2 C13.1 C14.1 C15.1 C16.1 C30.1 C32.1 P6.19 R23.1 R24.1 U1.8 U2.1 U2.18 U3.9 U3.11 U4.3 U4.4 U4.5 | length 2169.3
  Top Layer w10: C15.1@1209.37,2032.64 1238.35,2032.64 1245.25,2039.54 1245.25,2053.81 1253.45,2062.01 1300.49,2062.01 C10.1@1334.29,2028.21 ; U3.9@1259.11,1811.21 1228.23,1811.21 1219.86,1819.59 1219.86,1840.84 1228.91,1849.9 U3.11@1259.8,1849.9 1317.42,1849.9 v1(1332.68,1865.16) 1334.28,1865.16 C11.1@1376.18,1907.06 ; U1.8@1865.13,1670.83 U1.8@1864.15,1671.81 1864.15,1615.37 1916.34,1563.18 1916.34,1523.4 C7.1@1950.56,1489.17 C8.2@2019.69,1489.17 ; C8.2@2020.11,1489.6 2050.62,1489.6 v1(2083.66,1522.64)
  Top Layer w30: U4.4@1060.17,2526.61 U4.4@1064.11,2526.61 ; U4.5@1064.11,2440.09 U4.4@1064.11,2526.61 ; C16.1@1104.43,2628.11 1113.32,2619.22 U4.3@1113.32,2526.61 ; U4.3@1109.38,2526.61 U4.4@1064.11,2526.61 ; 1331.53,2335.22 1365.38,2335.22 1390.83,2309.77 C12.2@1399.01,2309.77 ; C10.1@1343.63,2028.21 C13.1@1343.63,2097.71 v1(1392.98,2097.71) ; C12.2@1398.65,2310.12 C14.1@1398.65,2434.82 ; v1(1622.05,1241.14) C1.1@1668.07,1241.14 ; C1.1@1668.66,1237.32 1707.93,1198.05 1921.02,1198.05 C2.1@1960.29,1237.32
  Bottom Layer w10: C30.1@1450.18,1616.84 C30.1@1450.22,1616.88
  Bottom Layer w30: v1@1362.51,1688.67 R23.1@1362.51,1617.03 C30.1@1449.99,1617.03 ; C32.1@1407.41,1281.27 1411.06,1284.92 1512.32,1284.92 1556.1,1241.14 v1(1622.05,1241.14) ; C30.1@1450.22,1616.88 R24.1@1520,1616.88
  other v1: 1361.72,1689.46
CHG: U1.20 U8.9 | length 1773.2
  Top Layer w10: U8.9@1483.46,1302.65 1488.13,1302.65 v1(1725.13,1539.65) ; U1.20@1994.07,1860.78 2368.7,1860.78 v1@2416.36,1908.44
  Bottom Layer w10: v1(1725.13,1539.65) 1711.2,1553.59 1711.2,1629.29 1759.49,1677.58 2293.64,1677.58 2389.35,1773.29 2389.35,1855.73 2416.36,1882.75 v1(2416.36,1920.25)
D+: P7.3 U6.6 | length 264.4
  Bottom Layer w10: U6.6@1937.93,1095.09 1938.1,1094.92 1938.1,958.79 1946.3,950.59 1993.33,950.59 2008.2,965.46 P7.3@2008.2,1013.8
D-: P7.2 U6.4 | length 397.3
  Bottom Layer w10: U6.4@1935.02,1143.35 1921.96,1143.35 1913.29,1134.68 1913.29,956.73 1938.43,931.59 2001.2,931.59 2033.79,964.18 P7.2@2033.79,1013.8
DGND: C3.2 C4.1 C5.2 C6.1 C18.1 C25.2 C33.1 C35.2 D3.2 D4.2 P5.2 P6.9 P6.17 P6.18 P7.5 P8.1 P9.1 R1.1 R12.1 R13.2 R26.2 R27.1 U1.23 U1.35 U1.47 U6.2 | length 4451.2
  Top Layer w10: R1.1@1525.92,1702.55 1597.29,1702.55 1637.42,1742.67 U1.47@1675.17,1742.67 1799.76,1742.67 1835.64,1778.56 v1(1835.64,1832.69) ; C5.2@1728.59,2067.48 1746.04,2050.03 U1.35@1746.04,1990.7 1746.04,1921.3 1835.14,1832.19 v1(1835.64,1832.69) ; C3.2@1863.08,1491.57 1863.08,1476.48 v1(1881.89,1457.68) ; U1.23@1987.86,1920.82 1923.77,1920.82 v1(1835.64,1832.69) ; U1.23@1995.05,1920.82 2031.35,1920.82 2048.32,1937.79 C4.1@2070.78,1937.79 2186.81,1937.79 2273.62,2024.61 ; R13.2@2204.8,2083.36 2263.55,2024.61 2273.62,2024.61 ; v1(2437.01,2024.61) 2273.62,2024.61
  Top Layer w30: P9.1@1982.2,2711.3 2048.96,2644.54 C18.1@2048.96,2486.08 D4.2@2248.32,2486.08 ; R12.1@2204.55,2183.13 2204.55,2485.91 ; R13.2@2204.8,2083.36 R12.1@2204.8,2182.89 ; D4.2@2248.58,2485.82 D3.2@2348.09,2485.82 ; D3.2@2348.23,2485.96 2479.9,2485.96 2529.95,2536.01 2638.67,2536.01 P5.2@2702.06,2472.62 ; P6.17@2495.29,1483.1 P6.18@2595.29,1483.1
  Bottom Layer w10: U6.2@1866.05,1123.6 1879.1,1123.6 1887.77,1132.27 1887.77,1145.32 1953.74,1211.29 1953.74,1427.17 1936.02,1444.88 1894.69,1444.88 v1(1881.89,1457.68) ; P7.5@1957.1,1013.8 1957.1,1075.61 2009.9,1128.41 R27.1@2009.9,1185.27 ; v1(2437.01,2024.61) 2443.33,2018.28 2443.33,1935.06 P6.9@2495.29,1883.1
  Bottom Layer w30: R27.1@2009.9,1185.27 2010.3,1185.67 C33.1@2079.3,1185.67 2236.07,1185.67 P8.1@2341.83,1079.91 ; C35.2@2283.64,1397.86 2337.89,1452.1 R26.2@2373.97,1452.1 2464.29,1452.1 P6.17@2495.29,1483.1 ; C25.2@2325.39,988.26 2341.83,1004.69 P8.1@2341.83,1070.97 ; P8.1@2341.83,1076.88 P8.1@2341.83,1079.91 ; P8.1@2341.83,1085.82 P8.1@2341.83,1079.91
EN1: U1.2 U8.6 | length 558.4
  Top Layer w10: U8.6@1508.66,1238.09 1509.34,1238.77 1536.1,1238.77 1641.43,1344.11 1641.43,1402.21 1660.95,1421.73 ; 1661.04,1421.73 1701.22,1461.91 1723.72,1461.91 v1(1751.97,1490.16) ; v1(1738.19,1618.11) 1746.04,1625.96 U1.2@1746.04,1671.81
  Bottom Layer w10: 1738.19,1604.33 1752.13,1590.39 v1@1752.13,1490.32
EN2: U1.12 U8.5 | length 712.4
  Top Layer w10: U8.5@1509.34,1219.09 U8.5@1508.66,1218.4 1542.6,1218.4 1660.43,1336.24 1660.43,1394.25 1709.09,1442.91 v1(1777.56,1442.91) ; U1.12@1944.34,1671.81 v1(1965.55,1650.59)
  Bottom Layer w10: v1(1777.56,1442.91) 1965.55,1630.91 v1(1965.55,1650.59)
EXT_I2C_SCL/TX: P6.3 R10.2 R12.2 U1.21 | length 993.6
  Top Layer w10: U1.21@1994.07,1880.47 2361.52,1880.47 2389.37,1908.32 2389.37,1931.43 v1@2413.64,1955.71 ; R12.2@2271.48,2183.13 2271.56,2183.06 R10.2@2336.62,2183.06 2304.13,2150.57 v1(2304.13,2132.87) ; R10.2@2346.34,2183.06 2380.03,2216.74 2427.06,2216.74 2460.7,2183.1 P6.3@2495.29,2183.1
  Bottom Layer w10: v1(2304.13,2132.87) 2410.02,2026.99 2410.02,1962.03 v1(2416.34,1955.71)
EXT_I2C_SDA/RX: P6.5 R11.2 R13.1 U1.22 | length 870.7
  Top Layer w10: U1.22@1995.05,1901.13 U1.22@1994.07,1900.15 2354.33,1900.15 2370.37,1916.19 2370.37,1947.91 2405.16,1982.7 2433.33,1982.7 2495.29,2044.66 P6.5@2495.29,2083.1 2460.61,2083.1 2427.3,2049.79 2380.27,2049.79 2346.59,2083.48 R11.2@2336.86,2083.48 ; R13.1@2271.73,2083.36 R11.2@2336.74,2083.36
EXT_SPI_CS: P6.11 U1.14 | length 524.1
  Top Layer w10: U1.14@1994.07,1742.67 2408.9,1742.67 v1(2416.34,1735.24)
  Bottom Layer w10: v1(2416.34,1735.24) 2447.43,1735.24 P6.11@2495.29,1783.1
EXT_SPI_MISO: P6.14 U1.16 | length 642.2
  Top Layer w10: U1.16@1994.07,1782.04 2434.79,1782.04 2477.26,1739.57 2538.82,1739.57 P6.14@2595.29,1683.1
EXT_SPI_MOSI: P6.12 U1.17 | length 629.6
  Top Layer w10: U1.17@1994.07,1801.73 2452.36,1801.73 2477.26,1826.63 2551.76,1826.63 P6.12@2595.29,1783.1
EXT_SPI_SCK: P6.13 U1.15 | length 529.3
  Top Layer w10: U1.15@1994.07,1762.36 2427.61,1762.36 P6.13@2495.29,1694.67
GND: BT.2 C24.1 C26.1 C27.1 C28.1 C29.1 C36.1 Q1.3 Q2.3 Q3.3 Q4.3 Q5.2 R6.1 R7.1 R8.1 R9.1 R15.1 R16.1 R17.1 R18.1 R19.1 R21.1 R23.2 R26.1 R34.1 R35.1 S1.1 U7.2 U8.4 U8.8 U8.17 U9.2 U10.2 | length 2536.7
  Top Layer w20: v1@1245.88,1282.01 R17.1@1245.88,1321.6 ; U8.4@1485.98,1192.91 v1@1554.13,1192.91 ; U8.8@1509.11,1281.77 1514.06,1281.77 v1(1541.34,1309.05) ; U10.2@2212.83,1291.3 2175.15,1291.3 2161.42,1277.56 2161.42,1246.59 2184.93,1223.08 2337.17,1223.08 2463.09,1097.16 S1.1@2463.09,954.23
  Top Layer w30: R19.1@1244.18,1148.88 1222.03,1148.88 1167.73,1203.18 1167.73,1239.7 1209.24,1281.2 v1@1245.08,1281.2 ; R19.1@1244.76,1149.47 R18.1@1244.76,1218.52 ; R17.1@1245.88,1321.6 R16.1@1245.88,1391.2 v1@1270.64,1391.2 ; C27.1@1452.63,1461.12 C26.1@1522.47,1461.12 ; R34.1@1522.47,1527.17 C26.1@1522.47,1461.12 ; v1@1564.46,1461.12 C26.1@1522.47,1461.12 ; U10.2@2212.89,1291.23 R15.1@2273.43,1291.23
  Bottom Layer w20: v1(1245.08,1279.53) 1251.5,1273.11 Q5.2@1282.68,1273.11 ; C24.1@1594.93,989.16 R21.1@1594.93,1058.62
  Bottom Layer w30: Q4.3@822.78,2797.94 R9.1@902.33,2718.39 ; Q2.3@868.76,824.48 870.31,824.48 R7.1@949.8,903.97 ; v1(1272.64,1390.75) 1272.64,1395.62 1325.84,1448.82 U7.2@1362.37,1448.82 ; v1@1319.98,1550.1 R23.2@1362.51,1550.1 ; C24.1@1595.36,988.73 1611.9,972.2 BT.2@1611.9,905 ; U9.2@2240.31,1290.09 2290.91,1290.09 v1(2320.12,1319.3) C29.1@2374.37,1319.3 ; R26.1@2373.97,1385.17 2374.37,1384.77 C29.1@2374.37,1319.3 ; R35.1@2441.9,1249.93 C36.1@2441.9,1319.23 2374.37,1319.23 C29.1@2374.37,1319.3 ; R8.1@2717.41,2764.59 Q3.3@2796.64,2843.82 ; R6.1@2762.68,949.11 Q1.3@2841.82,869.96
  other v1: 912.4,867.13 2802.17,908.46 2462.6,1026.57 1554.31,1193.09 1564.96,1461.61 1319.88,1550.2 865.16,2756.89 2754.73,2801.91
  other v3: 1453.93,1247.93
I2C_SCL_VCCA: R2.1 U1.42 U2.23 U4.8 | length 934.6
  Top Layer w10: U2.23@1211.29,2366.88 U4.8@1211.29,2439.55 ; U4.8@1211.74,2440 v1@1261.77,2440 ; v1(1481.3,2222.44) 1526.97,2176.77 1526.97,1946.18 1537.37,1935.78 R2.1@1537.37,1906.15 1602.42,1841.1 U1.42@1675.17,1841.1
  Bottom Layer w10: v1(1262.76,2440) v1@1480.32,2222.44
I2C_SDA_VCCA: R3.1 U1.43 U2.24 U4.7 | length 1141.2
  Top Layer w10: v1@1132.72,2366.14 1162.53,2395.95 ; U4.7@1162.53,2440 1162.53,2395.95 ; U2.24@1191.61,2366.88 1162.53,2395.95 ; v1(1413.39,2186.02) 1505.65,2093.76 1505.65,1880.67 1536.98,1849.34 R3.1@1536.98,1836.63 1552.2,1821.41 U1.43@1675.17,1821.41
  Bottom Layer w10: v1(1133.7,2366.14) 1113.19,2345.63 1113.19,2218.5 1145.67,2186.02 v1@1412.4,2186.02
INT_GA: U1.3 U2.12 | length 1497.1
  Top Layer w10: v1(1116.14,2143.7) 1068.9,2096.46 1068.9,1772.64 1250.42,1591.12 1749.37,1591.12 1765.18,1606.93 1765.18,1671.26 U1.3@1765.72,1671.81 ; U2.12@1290.03,2185.46 1318.9,2156.59 v1(1318.9,2143.7)
  Bottom Layer w10: v1@1127.66,2143.7 1149.83,2165.88 1190.43,2165.88 1212.6,2143.7 v1(1318.9,2143.7)
MOTOR1: Q3.2 R8.2 U1.19 | length 1567.1
  Top Layer w10: U1.19@1994.07,1841.1 2375.89,1841.1 2466.88,1932.09 2521.65,1932.09 2545.28,1955.71 v1(2545.28,2499.02)
  Bottom Layer w10: v1(2545.28,2499.02) R8.2@2763.1,2716.84 ; R8.2@2763.1,2717.27 2776.15,2717.27 Q3.2@2849.67,2790.79
MOTOR2: Q1.2 R6.2 U1.18 | length 1607.5
  Top Layer w10: U1.18@1994.07,1821.41 v1@2409.01,1821.41 ; v1(2389.35,1613.76) 2389.35,1601.99 2437.72,1553.61 2437.72,1515.27 2432.76,1510.31 2432.76,1188.3 v1(2683.56,937.5)
  Bottom Layer w10: v1(2389.35,1613.76) 2389.35,1746.42 2416.34,1773.41 v1(2416.34,1828.74) ; v1(2683.56,937.5) 2683.56,935.49 R6.2@2715.35,903.7 2715.35,890.37 Q1.2@2788.79,816.93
